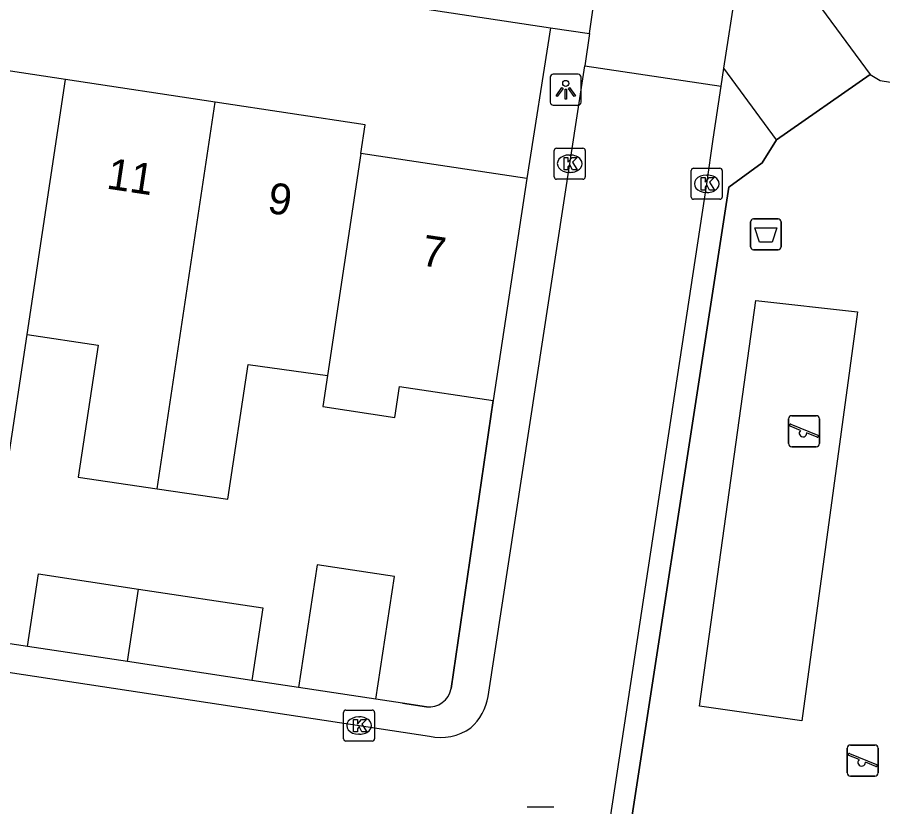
# Model space of a CAD drawing. Extents: x 163010 to 163853, y 382793 to 383982.
# Drawn here: x 163648.93 to 163676.84, y 383156.8 to 383182.27 of the extents above; entities that cross this region are included whole.
import ezdxf

# ---------------------------------------------------------------- set-up
doc = ezdxf.new("R2010")
doc.units = 0
for name, color, linetype in [('IMGEO_Afvalbak', 7, 'Continuous'), ('IMGEO_Groenvoorziening', 7, 'Continuous'), ('IMGEO_Hek', 7, 'Continuous'), ('IMGEO_Kolk', 7, 'Continuous'), ('IMGEO_Lichtpunt', 7, 'Continuous'), ('IMGEO_Muur', 7, 'Continuous'), ('IMGEO_Pand', 7, 'Continuous'), ('IMGEO_Pand_nummerreeks', 7, 'Continuous'), ('IMGEO_Rijbaan_lokaal_open', 7, 'Continuous'), ('IMGEO_Rioolput', 7, 'Continuous'), ('IMGEO_Speelvoorziening', 7, 'Continuous'), ('IMGEO_Voetpad_open', 7, 'Continuous')]:
    doc.layers.add(name, color=color, linetype=linetype)

msp = doc.modelspace()

# ---------------------------------------------------------------- linework, layer by layer
at = {"layer": 'IMGEO_Afvalbak'}
for p, q in [((163672.572, 383174.865), (163672.572, 383175.665)), ((163672.572, 383175.665), (163672.572, 383174.865)), ((163672.672, 383175.765), (163673.462, 383175.765)), ((163673.462, 383175.765), (163672.672, 383175.765)), ((163673.562, 383175.665), (163673.562, 383174.865)), ((163673.562, 383174.865), (163673.562, 383175.665)), ((163673.462, 383174.765), (163672.672, 383174.765)), ((163672.672, 383174.765), (163673.462, 383174.765))]:
    msp.add_line(p, q, dxfattribs=at)
msp.add_lwpolyline([(163672.715, 383175.479), (163673.419, 383175.479), (163673.27, 383175.009), (163672.864, 383175.009), (163672.715, 383175.479)], dxfattribs=at)
for centre, start, end in [((163672.672, 383175.665), 90, 180), ((163672.672, 383175.665), 90, 180), ((163673.462, 383175.665), 0, 90), ((163673.462, 383175.665), 360, 90), ((163672.672, 383174.865), 180, 270), ((163672.672, 383174.865), 180, 270), ((163673.462, 383174.865), 270, 0), ((163673.462, 383174.865), 270, 0)]:
    msp.add_arc(centre, 0.1, start, end, dxfattribs=at)
at = {"layer": 'IMGEO_Groenvoorziening'}
msp.add_lwpolyline([(163674.226, 383159.571), (163670.927, 383160.042), (163672.748, 383173.131), (163676.025, 383172.767), (163674.226, 383159.571)], dxfattribs=at)
at = {"layer": 'IMGEO_Hek'}
msp.add_lwpolyline([(163668.146, 383152.551), (163671.878, 383176.79), (163672.946, 383177.576), (163673.417, 383178.311), (163676.436, 383180.421), (163676.757, 383180.227), (163679.151, 383179.843), (163697.534, 383177.061), (163726.338, 383172.701), (163723.797, 383155.311), (163727.894, 383154.735), (163725.721, 383140.138), (163725.671, 383139.799), (163714.654, 383068.002), (163651.938, 383093.599), (163652.08, 383093.941), (163660.107, 383112.661)], dxfattribs=at)
at = {"layer": 'IMGEO_Kolk'}
for p, q in [((163666.245, 383177.118), (163666.245, 383177.97)), ((163666.32, 383178.044), (163667.172, 383178.044)), ((163667.246, 383177.97), (163667.246, 383177.118)), ((163666.733, 383177.824), (163666.758, 383177.824)), ((163670.738, 383177.395), (163671.59, 383177.395)), ((163667.172, 383177.044), (163666.32, 383177.044)), ((163666.756, 383177.264), (163666.731, 383177.264)), ((163670.663, 383176.469), (163670.663, 383177.321)), ((163671.151, 383177.175), (163671.176, 383177.175)), ((163671.664, 383177.321), (163671.664, 383176.469)), ((163671.174, 383176.615), (163671.149, 383176.615)), ((163671.59, 383176.395), (163670.738, 383176.395)), ((163659.453, 383158.996), (163659.453, 383159.848)), ((163659.528, 383159.922), (163660.38, 383159.922)), ((163660.454, 383159.848), (163660.454, 383158.996)), ((163659.941, 383159.702), (163659.966, 383159.702)), ((163660.38, 383158.922), (163659.528, 383158.922)), ((163659.964, 383159.142), (163659.939, 383159.142))]:
    msp.add_line(p, q, dxfattribs=at)
for points in [[(163666.245, 383177.118), (163666.245, 383177.97)], [(163666.32, 383178.044), (163667.172, 383178.044)], [(163667.246, 383177.97), (163667.246, 383177.118)], [(163666.566, 383177.744), (163666.689, 383177.744), (163666.689, 383177.593), (163666.819, 383177.744), (163666.983, 383177.744), (163666.837, 383177.593), (163666.99, 383177.344), (163666.838, 383177.344), (163666.753, 383177.508), (163666.689, 383177.441), (163666.689, 383177.344), (163666.566, 383177.344), (163666.566, 383177.744)], [(163670.738, 383177.395), (163671.59, 383177.395)], [(163667.172, 383177.044), (163666.32, 383177.044)], [(163670.663, 383176.469), (163670.663, 383177.321)], [(163670.984, 383177.095), (163671.107, 383177.095), (163671.107, 383176.944), (163671.237, 383177.095), (163671.401, 383177.095), (163671.255, 383176.944), (163671.408, 383176.695), (163671.256, 383176.695), (163671.171, 383176.859), (163671.107, 383176.792), (163671.107, 383176.695), (163670.984, 383176.695), (163670.984, 383177.095)], [(163671.664, 383177.321), (163671.664, 383176.469)], [(163671.59, 383176.395), (163670.738, 383176.395)], [(163659.453, 383158.996), (163659.453, 383159.848)], [(163659.528, 383159.922), (163660.38, 383159.922)], [(163660.454, 383159.848), (163660.454, 383158.996)], [(163659.774, 383159.622), (163659.897, 383159.622), (163659.897, 383159.471), (163660.027, 383159.622), (163660.191, 383159.622), (163660.045, 383159.471), (163660.198, 383159.222), (163660.046, 383159.222), (163659.961, 383159.386), (163659.897, 383159.319), (163659.897, 383159.222), (163659.774, 383159.222), (163659.774, 383159.622)], [(163660.38, 383158.922), (163659.528, 383158.922)]]:
    msp.add_lwpolyline(points, dxfattribs=at)
for centre, start, end in [((163666.322, 383177.968), 91.552, 178.448), ((163666.322, 383177.968), 91.552, 178.448), ((163667.17, 383177.968), 1.552, 88.448), ((163667.17, 383177.968), 1.552, 88.448), ((163670.74, 383177.319), 91.552, 178.448), ((163670.74, 383177.319), 91.552, 178.448), ((163671.588, 383177.319), 1.552, 88.448), ((163671.588, 383177.319), 1.552, 88.448), ((163666.322, 383177.12), 181.552, 268.448), ((163666.322, 383177.12), 181.552, 268.448), ((163667.17, 383177.12), 271.552, 358.448), ((163667.17, 383177.12), 271.552, 358.448), ((163670.74, 383176.471), 181.552, 268.448), ((163670.74, 383176.471), 181.552, 268.448), ((163671.588, 383176.471), 271.552, 358.448), ((163671.588, 383176.471), 271.552, 358.448), ((163659.53, 383159.846), 91.552, 178.448), ((163659.53, 383159.846), 91.552, 178.448), ((163660.378, 383159.846), 1.552, 88.448), ((163660.378, 383159.846), 1.552, 88.448), ((163659.53, 383158.998), 181.552, 268.448), ((163659.53, 383158.998), 181.552, 268.448), ((163660.378, 383158.998), 271.552, 358.448), ((163660.378, 383158.998), 271.552, 358.448)]:
    msp.add_arc(centre, 0.0765, start, end, dxfattribs=at)
for centre, major_axis, ratio, start_param, end_param in [((163666.732, 383177.544), (-0.387, 0.002), 0.722429, 4.712389, 7.853982), ((163666.757, 383177.544), (-0.39, 0.002), 0.717154, 1.570796, 4.712389), ((163671.15, 383176.895), (-0.387, 0.002), 0.722429, 4.712389, 7.853982), ((163671.175, 383176.895), (-0.39, 0.002), 0.717154, 1.570796, 4.712389), ((163659.94, 383159.422), (-0.387, 0.002), 0.722429, 4.712389, 7.853982), ((163659.965, 383159.422), (-0.39, 0.002), 0.717154, 1.570796, 4.712389)]:
    msp.add_ellipse(centre, major_axis=major_axis, ratio=ratio, start_param=start_param, end_param=end_param, dxfattribs=at)
at = {"layer": 'IMGEO_Lichtpunt'}
for p, q in [((163667.02, 383180.429), (163666.212, 383180.429)), ((163667.02, 383180.429), (163666.212, 383180.429)), ((163666.118, 383180.334), (163666.118, 383179.527)), ((163666.118, 383180.334), (163666.118, 383179.527)), ((163667.114, 383179.527), (163667.114, 383180.334)), ((163667.114, 383179.527), (163667.114, 383180.334)), ((163666.212, 383179.433), (163667.02, 383179.433)), ((163666.212, 383179.433), (163667.02, 383179.433))]:
    msp.add_line(p, q, dxfattribs=at)
for points in [[(163666.492, 383179.998), (163666.531, 383179.97), (163666.343, 383179.708), (163666.305, 383179.735), (163666.492, 383179.998)], [(163666.594, 383179.95), (163666.641, 383179.95), (163666.641, 383179.628), (163666.594, 383179.628), (163666.594, 383179.95)], [(163666.704, 383179.97), (163666.742, 383179.997), (163666.929, 383179.735), (163666.89, 383179.707), (163666.704, 383179.97)]]:
    msp.add_lwpolyline(points, dxfattribs=at)
msp.add_circle((163666.617, 383180.132), 0.0994, dxfattribs=at)
for centre, start, end in [((163666.212, 383180.334), 90, 180), ((163666.212, 383180.334), 90, 180), ((163667.02, 383180.334), 0, 90), ((163667.02, 383180.334), 0, 90), ((163666.212, 383179.527), 180, 270), ((163666.212, 383179.527), 180, 270), ((163667.02, 383179.527), 270, 0), ((163667.02, 383179.527), 270, 360)]:
    msp.add_arc(centre, 0.0946, start, end, dxfattribs=at)
at = {"layer": 'IMGEO_Muur'}
for points in [[(163662.925, 383160.612), (163664.28, 383169.904)], [(163661.357, 383160.14), (163662.122, 383160.024)]]:
    msp.add_lwpolyline(points, dxfattribs=at)
msp.add_arc((163662.201, 383160.758), 0.738, 263.8335, 348.5937, dxfattribs=at)
at = {"layer": 'IMGEO_Pand'}
for points in [[(163650.484, 383180.259), (163645.651, 383180.987)], [(163649.246, 383172.032), (163650.484, 383180.259)], [(163655.316, 383179.53), (163650.484, 383180.259)], [(163653.44, 383167.06), (163655.316, 383179.53)], [(163660.008, 383177.875), (163660.148, 383178.802), (163655.316, 383179.53)], [(163660.008, 383177.875), (163658.93, 383170.71)], [(163665.36, 383177.068), (163660.008, 383177.875)], [(163665.36, 383177.068), (163664.28, 383169.904)], [(163643.779, 383168.548), (163646.192, 383168.184), (163648.612, 383167.819), (163649.246, 383172.032)], [(163649.246, 383172.032), (163651.542, 383171.686), (163650.9, 383167.431), (163653.44, 383167.06)], [(163653.44, 383167.06), (163655.725, 383166.727), (163656.381, 383171.07), (163658.93, 383170.71)], [(163658.93, 383170.71), (163658.78, 383169.71), (163661.108, 383169.359), (163661.258, 383170.359), (163664.28, 383169.904)], [(163660.492, 383160.272), (163661.094, 383164.226), (163658.602, 383164.603), (163658, 383160.649)], [(163649.26, 383161.972), (163649.617, 383164.315), (163652.84, 383163.825)], [(163652.487, 383161.483), (163652.84, 383163.825)], [(163652.84, 383163.825), (163656.854, 383163.214), (163656.498, 383160.876)], [(163652.487, 383161.483), (163649.26, 383161.972)], [(163656.498, 383160.876), (163652.487, 383161.483)], [(163660.492, 383160.272), (163658, 383160.649)]]:
    msp.add_lwpolyline(points, dxfattribs=at)
at = {"layer": 'IMGEO_Rijbaan_lokaal_open'}
for points in [[(163667.379, 383181.747), (163668.321, 383188.294)], [(163671.717, 383180.628), (163672.507, 383185.752)], [(163667.379, 383181.747), (163667.378, 383181.74), (163667.228, 383180.698)], [(163664.116, 383160.362), (163666.553, 383176.284), (163667.228, 383180.698)], [(163667.228, 383180.698), (163671.627, 383180.045)], [(163671.627, 383180.045), (163671.717, 383180.628)], [(163667.475, 383152.649), (163671.164, 383176.895), (163671.375, 383178.333), (163671.627, 383180.045)], [(163545.77, 383176.763), (163547.368, 383176.527), (163662.219, 383159.074)]]:
    msp.add_lwpolyline(points, dxfattribs=at)
for centre, radius, start, end in [((163662.466, 383160.614), 1.669, 310.7258, 351.3188), ((163662.577, 383160.718), 1.682, 257.7154, 305.5471)]:
    msp.add_arc(centre, radius, start, end, dxfattribs=at)
at = {"layer": 'IMGEO_Rioolput'}
msp.add_line((163665.376, 383156.804), (163666.228, 383156.804), dxfattribs=at)
msp.add_lwpolyline([(163665.376, 383156.804), (163666.228, 383156.804)], dxfattribs=at)
at = {"layer": 'IMGEO_Speelvoorziening'}
for p, q in [((163673.804, 383168.514), (163673.804, 383169.314)), ((163673.804, 383169.314), (163673.804, 383168.514)), ((163673.904, 383169.414), (163674.694, 383169.414)), ((163674.694, 383169.414), (163673.904, 383169.414)), ((163674.794, 383169.314), (163674.794, 383168.514)), ((163674.794, 383168.514), (163674.794, 383169.314)), ((163674.187, 383168.942), (163673.848, 383169.079)), ((163673.873, 383169.139), (163674.749, 383168.786)), ((163674.725, 383168.726), (163674.385, 383168.863)), ((163674.694, 383168.414), (163673.904, 383168.414)), ((163673.904, 383168.414), (163674.694, 383168.414)), ((163675.696, 383157.894), (163675.696, 383158.694)), ((163675.696, 383158.694), (163675.696, 383157.894)), ((163675.796, 383158.794), (163676.586, 383158.794)), ((163676.586, 383158.794), (163675.796, 383158.794)), ((163676.686, 383158.694), (163676.686, 383157.894)), ((163676.686, 383157.894), (163676.686, 383158.694)), ((163676.079, 383158.322), (163675.74, 383158.459)), ((163675.765, 383158.519), (163676.641, 383158.166)), ((163676.617, 383158.106), (163676.277, 383158.243)), ((163676.586, 383157.794), (163675.796, 383157.794)), ((163675.796, 383157.794), (163676.586, 383157.794))]:
    msp.add_line(p, q, dxfattribs=at)
for centre, radius, start, end in [((163673.904, 383169.314), 0.1, 90, 180), ((163673.904, 383169.314), 0.1, 90, 180), ((163674.694, 383169.314), 0.1, 0, 90), ((163674.694, 383169.314), 0.1, 360, 90), ((163673.861, 383169.109), 0.0327, 68.078, 248.078), ((163674.266, 383168.852), 0.12, 130.9928, 5.1632), ((163674.737, 383168.756), 0.0327, 248.078, 68.078), ((163673.904, 383168.514), 0.1, 180, 270), ((163673.904, 383168.514), 0.1, 180, 270), ((163674.694, 383168.514), 0.1, 270, 0), ((163674.694, 383168.514), 0.1, 270, 0), ((163675.796, 383158.694), 0.1, 90, 180), ((163675.796, 383158.694), 0.1, 90, 180), ((163676.586, 383158.694), 0.1, 0, 90), ((163676.586, 383158.694), 0.1, 360, 90), ((163675.753, 383158.489), 0.0327, 68.078, 248.078), ((163676.158, 383158.232), 0.12, 130.9928, 5.1632), ((163676.629, 383158.136), 0.0327, 248.078, 68.078), ((163675.796, 383157.894), 0.1, 180, 270), ((163675.796, 383157.894), 0.1, 180, 270), ((163676.586, 383157.894), 0.1, 270, 0), ((163676.586, 383157.894), 0.1, 270, 0)]:
    msp.add_arc(centre, radius, start, end, dxfattribs=at)
at = {"layer": 'IMGEO_Voetpad_open'}
for points in [[(163548.798, 383199.652), (163666.122, 383181.928)], [(163672.507, 383185.752), (163676.436, 383180.421)], [(163666.122, 383181.928), (163665.36, 383177.068)], [(163666.122, 383181.928), (163667.379, 383181.747)], [(163673.417, 383178.311), (163671.717, 383180.628)], [(163676.436, 383180.421), (163673.417, 383178.311)], [(163676.436, 383180.421), (163676.757, 383180.227), (163679.151, 383179.843), (163697.534, 383177.061)], [(163673.417, 383178.311), (163672.946, 383177.576), (163671.878, 383176.79), (163668.146, 383152.551)], [(163664.28, 383169.904), (163662.925, 383160.612)], [(163649.26, 383161.972), (163646.837, 383162.339)], [(163658, 383160.649), (163656.498, 383160.876)], [(163662.122, 383160.024), (163661.357, 383160.14), (163660.492, 383160.272)]]:
    msp.add_lwpolyline(points, dxfattribs=at)
msp.add_arc((163662.201, 383160.758), 0.738, 263.8335, 348.5937, dxfattribs=at)

# ---------------------------------------------------------------- texts
at = {"layer": 'IMGEO_Pand_nummerreeks'}
for s, rotation, p in [('11', 351.4276, (163651.779, 383176.746)), ('9', 351.4276, (163656.965, 383175.965)), ('7', 351.4228, (163661.924, 383174.269))]:
    msp.add_text(s, height=1, rotation=rotation, dxfattribs=at).set_placement(p)

doc.saveas('drawing.dxf')
